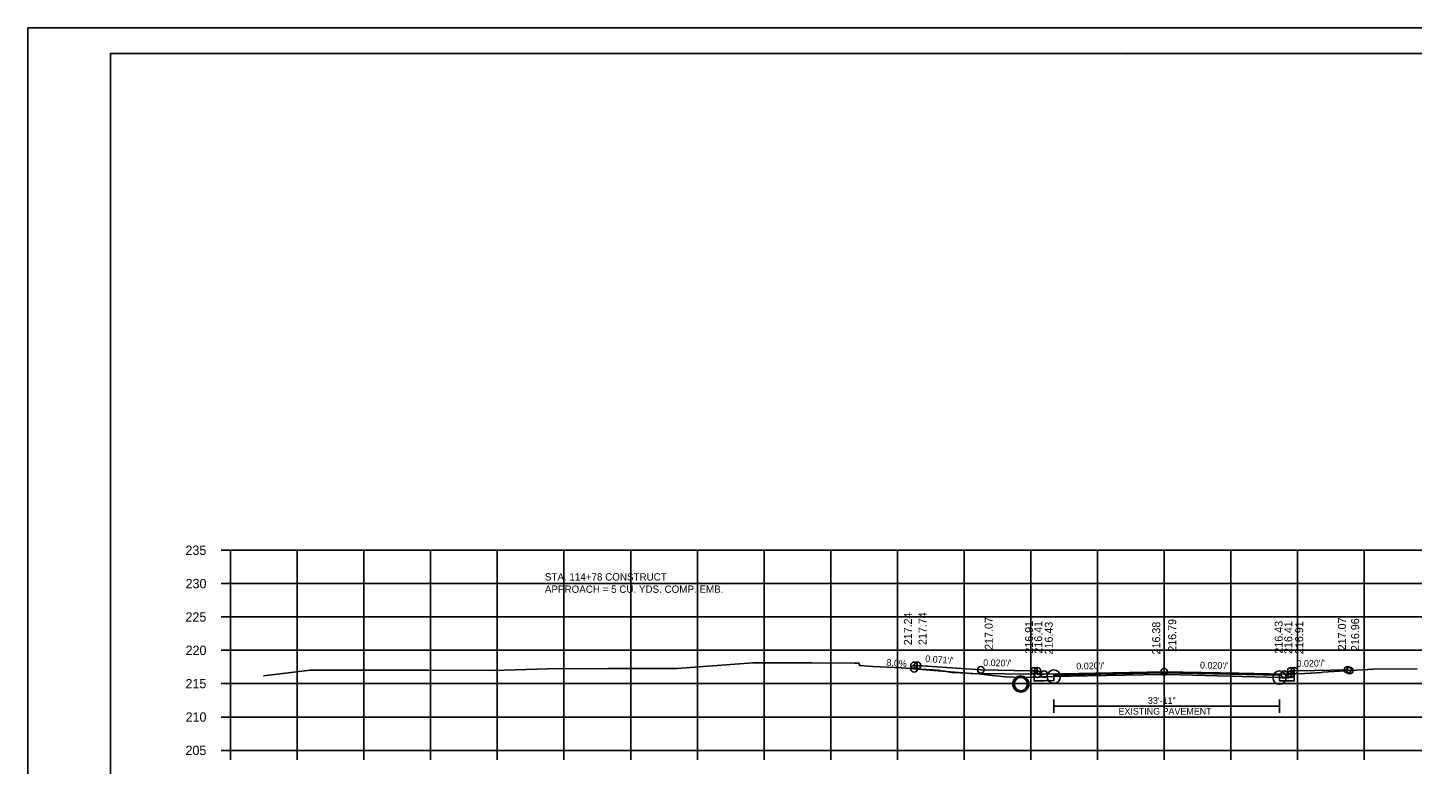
# Model space of a CAD drawing. Extents: x 1368968 to 1369915, y 377395 to 380381.
# Drawn here: x 1369581.4 to 1369789, y 378564.3 to 378674.7 of the extents above; entities that cross this region are included whole.
import ezdxf

# ---------------------------------------------------------------- set-up
doc = ezdxf.new("R2010")
doc.units = 0
for name, color, linetype in [('Default', 7, 'Continuous'), ('S_BORDER_NO_PLOT', 7, 'Continuous'), ('S_BREAKLINE_ANNOT', 7, 'Continuous'), ('S_BRIDGE', 7, 'Continuous'), ('S_BRIDGE_ANNOT', 7, 'Continuous'), ('S_CONTOUR_MINOR', 7, 'Continuous'), ('S_CROSS_DRAIN', 7, 'Continuous'), ('S_CTL_TABLE', 7, 'Continuous'), ('S_CURB_ANNOT', 7, 'Continuous'), ('S_DITCHLINE_ANNOT', 7, 'Continuous'), ('S_DROP_INLET', 7, 'Continuous'), ('S_EXIST_ROW_ANNOT', 7, 'Continuous'), ('S_EXISTING_ALIGNMENT_ANNOT', 7, 'Continuous'), ('S_FENCE', 7, 'Continuous')]:
    doc.layers.add(name, color=color, linetype=linetype)

msp = doc.modelspace()

# ---------------------------------------------------------------- linework, layer by layer
at = {"layer": 'Default'}
msp.add_line((1369735.22, 378577.65), (1369735.22, 378576.82), dxfattribs=at)
at = {"layer": 'S_BORDER_NO_PLOT'}
msp.add_lwpolyline([(1369732.27, 378578.28), (1369732.28, 378576.77), (1369733.78, 378576.8), (1369735.22, 378576.82), (1369735.22, 378577.65), (1369751.78, 378577.99), (1369769.08, 378577.64), (1369769.08, 378576.81), (1369769.78, 378576.8), (1369771.28, 378576.77), (1369771.29, 378578.28)], dxfattribs=at)
at = {"layer": 'S_BREAKLINE_ANNOT'}
for p, q in [((1369610.38, 378596.37), (1369611.78, 378596.37)), ((1369611.78, 378566.37), (1369611.78, 378596.37)), ((1369610.38, 378591.37), (1369611.78, 378591.37)), ((1369610.38, 378586.37), (1369611.78, 378586.37)), ((1369610.38, 378581.37), (1369611.78, 378581.37)), ((1369610.38, 378576.37), (1369611.78, 378576.37)), ((1369610.38, 378571.37), (1369611.78, 378571.37)), ((1369610.38, 378566.37), (1369611.78, 378566.37)), ((1369611.78, 378566.37), (1369891.78, 378566.37)), ((1369611.78, 378564.97), (1369611.78, 378566.37)), ((1369621.78, 378564.97), (1369621.78, 378566.37)), ((1369631.78, 378564.97), (1369631.78, 378566.37)), ((1369641.78, 378564.97), (1369641.78, 378566.37)), ((1369651.78, 378564.97), (1369651.78, 378566.37)), ((1369661.78, 378564.97), (1369661.78, 378566.37)), ((1369671.78, 378564.97), (1369671.78, 378566.37)), ((1369681.78, 378564.97), (1369681.78, 378566.37)), ((1369691.78, 378564.97), (1369691.78, 378566.37)), ((1369701.78, 378564.97), (1369701.78, 378566.37)), ((1369711.78, 378564.97), (1369711.78, 378566.37)), ((1369721.78, 378564.97), (1369721.78, 378566.37)), ((1369731.78, 378564.97), (1369731.78, 378566.37)), ((1369741.78, 378564.97), (1369741.78, 378566.37)), ((1369751.78, 378564.97), (1369751.78, 378566.37)), ((1369761.78, 378564.97), (1369761.78, 378566.37)), ((1369771.78, 378564.97), (1369771.78, 378566.37)), ((1369781.78, 378564.97), (1369781.78, 378566.37))]:
    msp.add_line(p, q, dxfattribs=at)
at = {"layer": 'S_BRIDGE_ANNOT'}
for p, q in [((1369593.78, 378670.83), (1369909.96, 378670.83)), ((1369593.78, 378465.37), (1369593.78, 378670.83)), ((1369746.3, 378670.57), (1369746.3, 378670.57)), ((1369746.3, 378670.57), (1369746.3, 378670.57))]:
    msp.add_line(p, q, dxfattribs=at)
at = {"layer": 'S_CROSS_DRAIN'}
for p, q in [((1369711.78, 378578.77), (1369722.78, 378577.88)), ((1369732.78, 378577.78), (1369722.78, 378577.88)), ((1369735.22, 378573), (1369769.08, 378573))]:
    msp.add_line(p, q, dxfattribs=at)
at = {"layer": 'S_CTL_TABLE'}
msp.add_lwpolyline([(1369616.71, 378577.52), (1369623.73, 378578.37), (1369624.1, 378578.38), (1369641.3, 378578.39), (1369651.23, 378578.36), (1369659.31, 378578.59), (1369668.41, 378578.65), (1369678.69, 378578.65), (1369690.12, 378579.5), (1369698.93, 378579.49), (1369705.33, 378579.46), (1369706, 378579.46), (1369706.12, 378579.09), (1369706.13, 378579.08), (1369708.07, 378578.95), (1369712.43, 378578.73), (1369713.53, 378578.65), (1369717.87, 378578.39), (1369719.13, 378578.17), (1369719.61, 378578.07), (1369719.94, 378578.03), (1369721.23, 378577.98), (1369723.92, 378577.84), (1369726.05, 378577.57), (1369727.96, 378577.4), (1369730.33, 378577.28), (1369730.49, 378577.27), (1369732.03, 378577.32), (1369735.19, 378577.42), (1369735.22, 378577.42), (1369740.33, 378577.53), (1369751.32, 378577.76), (1369752.34, 378577.73), (1369769.08, 378577.27), (1369769.41, 378577.24), (1369770.44, 378577.25), (1369770.95, 378577.67), (1369771.11, 378577.83), (1369772.86, 378577.9), (1369775.39, 378578.06), (1369775.47, 378578.06), (1369775.53, 378578.07), (1369783.16, 378578.55), (1369789.73, 378578.6)], dxfattribs=at)
at = {"layer": 'S_CURB_ANNOT'}
msp.add_lwpolyline([(1369714.27, 378578.61), (1369714.27, 378579.11), (1369714.77, 378579.11), (1369722.09, 378578.59), (1369724.27, 378578.44), (1369729.27, 378578.34), (1369731.7, 378578.29), (1369732.27, 378578.28), (1369732.27, 378578.28), (1369732.77, 378578.28), (1369732.78, 378577.78), (1369733.78, 378577.8), (1369733.78, 378577.8), (1369751.78, 378578.16), (1369751.78, 378578.16), (1369762.99, 378577.93), (1369769.78, 378577.8), (1369770.78, 378577.78), (1369770.79, 378578.28), (1369771, 378578.28), (1369771.29, 378578.28), (1369774.29, 378578.34), (1369774.29, 378578.34), (1369779.29, 378578.44), (1369779.39, 378578.4), (1369779.61, 378578.33)], dxfattribs=at)
at = {"layer": 'S_DITCHLINE_ANNOT'}
for p, q in [((1369611.78, 378596.37), (1369891.78, 378596.37)), ((1369611.78, 378566.37), (1369611.78, 378596.37)), ((1369621.78, 378566.37), (1369621.78, 378596.37)), ((1369631.78, 378566.37), (1369631.78, 378596.37)), ((1369641.78, 378566.37), (1369641.78, 378596.37)), ((1369651.78, 378566.37), (1369651.78, 378596.37)), ((1369661.78, 378566.37), (1369661.78, 378596.37)), ((1369671.78, 378566.37), (1369671.78, 378596.37)), ((1369681.78, 378566.37), (1369681.78, 378596.37)), ((1369691.78, 378566.37), (1369691.78, 378596.37)), ((1369701.78, 378566.37), (1369701.78, 378596.37)), ((1369711.78, 378566.37), (1369711.78, 378596.37)), ((1369721.78, 378566.37), (1369721.78, 378596.37)), ((1369731.78, 378566.37), (1369731.78, 378596.37)), ((1369741.78, 378566.37), (1369741.78, 378596.37)), ((1369751.78, 378566.37), (1369751.78, 378596.37)), ((1369761.78, 378566.37), (1369761.78, 378596.37)), ((1369771.78, 378566.37), (1369771.78, 378596.37)), ((1369781.78, 378566.37), (1369781.78, 378596.37)), ((1369611.78, 378591.37), (1369891.78, 378591.37)), ((1369611.78, 378586.37), (1369891.78, 378586.37)), ((1369611.78, 378581.37), (1369891.78, 378581.37)), ((1369611.78, 378576.37), (1369891.78, 378576.37)), ((1369611.78, 378571.37), (1369891.78, 378571.37)), ((1369611.78, 378566.37), (1369891.78, 378566.37))]:
    msp.add_line(p, q, dxfattribs=at)
at = {"layer": 'S_DROP_INLET'}
msp.add_line((1369581.38, 378674.72), (1369914.71, 378674.72), dxfattribs=at)
for points in [[(1369581.37, 378674.72), (1369914.71, 378674.72), (1369914.71, 378461.38), (1369581.37, 378461.38)], [(1369827.7, 378670.83), (1369827.7, 378660.95), (1369863.43, 378660.95), (1369863.43, 378658.03), (1369886.63, 378658.03), (1369886.63, 378633.69), (1369909.96, 378633.69), (1369909.96, 378465.37), (1369593.78, 378465.37), (1369593.78, 378670.83)]]:
    msp.add_lwpolyline(points, close=True, dxfattribs=at)
for centre, radius in [((1369714.27, 378579.11), 0.5), ((1369714.77, 378579.11), 0.5), ((1369714.27, 378578.61), 0.5), ((1369724.27, 378578.44), 0.5), ((1369730.28, 378576.31), 1.21), ((1369732.27, 378578.28), 0.5), ((1369732.77, 378578.28), 0.5), ((1369732.78, 378577.78), 0.5), ((1369733.78, 378577.8), 0.5), ((1369733.78, 378577.8), 0.5), ((1369735.22, 378577.42), 1), ((1369751.78, 378578.16), 0.5), ((1369769.08, 378577.27), 1), ((1369769.78, 378577.8), 0.5), ((1369769.78, 378577.8), 0.5), ((1369770.78, 378577.78), 0.5), ((1369770.79, 378578.28), 0.5), ((1369771.29, 378578.28), 0.5), ((1369779.29, 378578.44), 0.5), ((1369779.61, 378578.33), 0.5)]:
    msp.add_circle(centre, radius, dxfattribs=at)
at = {"layer": 'S_EXIST_ROW_ANNOT'}
for p, q in [((1369735.22, 378572), (1369735.22, 378574)), ((1369769.08, 378572), (1369769.08, 378574))]:
    msp.add_line(p, q, dxfattribs=at)
msp.add_circle((1369730.28, 378576.31), 1, dxfattribs=at)
at = {"layer": 'S_EXISTING_ALIGNMENT_ANNOT'}
msp.add_line((1369751.78, 378577.75), (1369751.78, 378587.75), dxfattribs=at)

# ---------------------------------------------------------------- texts
at = {"layer": 'S_BRIDGE'}
for s, p in [('235', (1369605.03, 378595.67)), ('230', (1369605.05, 378590.67)), ('225', (1369605.03, 378585.67)), ('220', (1369605.05, 378580.67)), ('215', (1369605.03, 378575.67)), ('210', (1369605.05, 378570.67)), ('205', (1369605.03, 378565.67))]:
    msp.add_text(s, height=1.4, dxfattribs=at).set_placement(p)
at = {"layer": 'S_CONTOUR_MINOR'}
for s, p in [('STA. 114+78 CONSTRUCT ', (1369658.92, 378591.83)), ('APPROACH = 5 CU. YDS. COMP. EMB.', (1369658.92, 378589.99))]:
    msp.add_text(s, height=1.1, dxfattribs=at).set_placement(p)
at = {"layer": 'S_CROSS_DRAIN'}
msp.add_text('8.0%', height=1, rotation=355.3744, dxfattribs=at).set_placement((1369710.1, 378579.07))
at = {"layer": 'S_EXIST_ROW_ANNOT'}
for s, p in [('33\'-11"', (1369749.34, 378573.34)), ('EXISTING PAVEMENT', (1369744.92, 378571.73))]:
    msp.add_text(s, height=1, dxfattribs=at).set_placement(p)
at = {"layer": 'S_EXISTING_ALIGNMENT_ANNOT'}
for s, p in [('217.24', (1369713.95, 378582.13)), ('217.74', (1369716.14, 378582.16)), ('217.07', (1369726.07, 378581.44)), ('216.91', (1369732.11, 378580.87)), ('216.41', (1369733.49, 378580.87)), ('216.43', (1369735.07, 378580.75)), ('216.38', (1369751.18, 378580.75)), ('216.79', (1369753.58, 378581.16)), ('216.43', (1369769.54, 378580.87)), ('216.41', (1369770.98, 378580.82)), ('216.91', (1369772.62, 378580.81)), ('217.07', (1369779.04, 378581.37)), ('216.96', (1369781.01, 378581.26))]:
    msp.add_text(s, height=1.2, rotation=90, dxfattribs=at).set_placement(p)
at = {"layer": 'S_FENCE'}
for s, rotation, p in [("0.071'/'", 355.9476, (1369715.92, 378579.63)), ("0.020'/'", 358.8542, (1369724.63, 378579.03)), ("0.020'/'", 1.1458, (1369738.61, 378578.49)), ("0.020'/'", 358.8542, (1369757.14, 378578.65)), ("0.020'/'", 1.1457, (1369771.63, 378578.88))]:
    msp.add_text(s, height=1, rotation=rotation, dxfattribs=at).set_placement(p)

doc.saveas('drawing.dxf')
